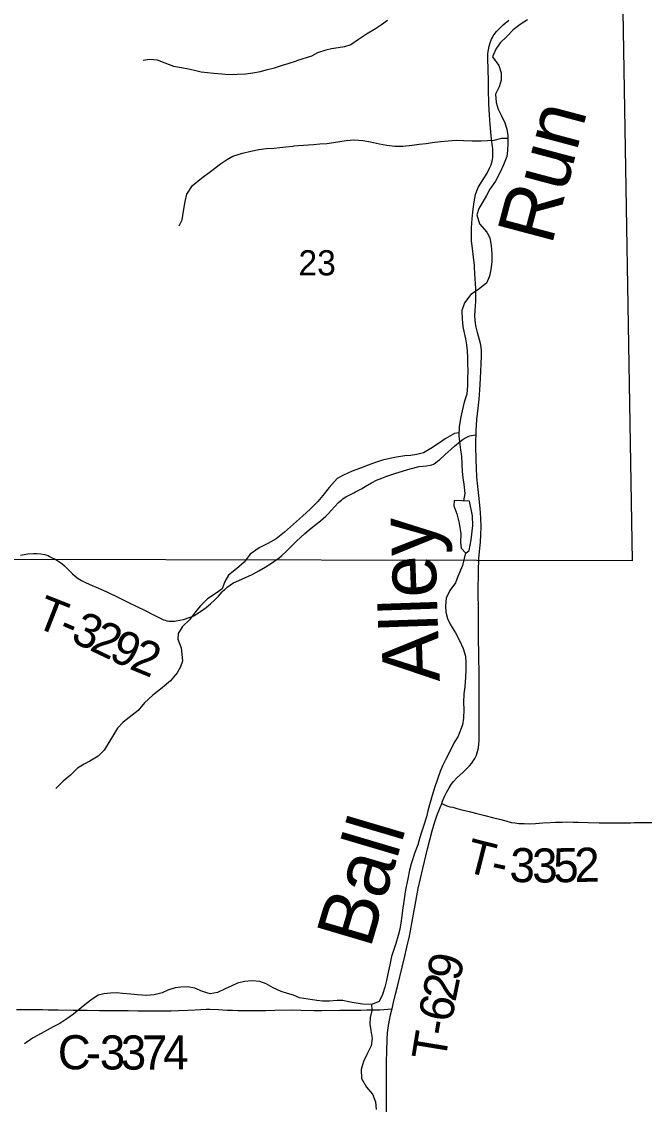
# Model space of a CAD drawing. Extents: x 1874609 to 2204689, y 815661 to 1281160.
# Drawn here: x 2035487 to 2040964, y 935118 to 944638 of the extents above; entities that cross this region are included whole.
import ezdxf

# ---------------------------------------------------------------- set-up
doc = ezdxf.new("R2010")
doc.units = 0
for name, color, linetype in [('GM_X_County_Road', 7, 'Continuous'), ('GM_X_County_Road_Text', 7, 'Continuous'), ('GM_X_Minor_Lake', 7, 'Continuous'), ('GM_X_Minor_River', 7, 'Continuous'), ('GM_X_Minor_River_Text', 7, 'Continuous'), ('GM_X_Section', 7, 'Continuous'), ('GM_X_Section_Text', 7, 'Continuous'), ('GM_X_Township_Road', 7, 'Continuous'), ('GM_X_Township_Road_Text', 7, 'Continuous')]:
    doc.layers.add(name, color=color, linetype=linetype)

msp = doc.modelspace()

# ---------------------------------------------------------------- linework, layer by layer
at = {"layer": 'GM_X_County_Road'}
msp.add_lwpolyline([(2035441, 935952.1), (2035490.1, 935952.7), (2035571.9, 935953), (2035621, 935952.2), (2035670.1, 935950.8), (2035719.3, 935948), (2035807.1, 935948.3), (2035940.9, 935947), (2036011.3, 935946.3), (2036064.3, 935945.8), (2036170.5, 935944.7), (2036315.9, 935943.3), (2036424.4, 935942.3), (2036507.5, 935941.5), (2036588.2, 935940.7), (2036589.7, 935940.7), (2036670.9, 935941.5), (2036736.2, 935941.2), (2036801.6, 935941.1), (2036867, 935942.4), (2036948.6, 935946), (2037013.7, 935949.5), (2037062.3, 935951.9), (2037110.3, 935954.2), (2037141.5, 935954.2), (2037217.8, 935951.4), (2037293.9, 935947.3), (2037340.5, 935945.2), (2037388, 935943.6), (2037420.1, 935942.9), (2037452.6, 935942.7), (2037632.7, 935943.6), (2037714.5, 935944.9), (2037861.8, 935948.2), (2037943.8, 935947.8), (2038058.3, 935944.2), (2038123.4, 935943.5), (2038286.9, 935946.8), (2038385, 935946.9), (2038471.2, 935947.2), (2038523.9, 935947.9), (2038569.5, 935948.1), (2038600, 935948.8), (2038638.7, 935950.3), (2038673.4, 935951.8), (2038707.6, 935954.5), (2038745, 935958)], dxfattribs=at)
at = {"layer": 'GM_X_Minor_Lake'}
for points in [[(2039292.2, 940427), (2039288.6, 940380.9), (2039313.2, 940311), (2039334, 940227), (2039348.8, 940135), (2039345.5, 940060.8), (2039352, 940008.8), (2039392.4, 939965.1), (2039424.2, 939989.4), (2039441.4, 940081.8), (2039454.3, 940208.1), (2039453.5, 940294.2), (2039426.3, 940422.2)], [(2039426.3, 940422.2), (2039292.2, 940427)]]:
    msp.add_lwpolyline(points, dxfattribs=at)
at = {"layer": 'GM_X_Minor_River'}
for points in [[(2038705.7, 944648.6), (2038652, 944610), (2038598.2, 944573.5), (2038520.6, 944526.7), (2038450.9, 944480), (2038383.2, 944435.3), (2038327.3, 944416.7), (2038271.4, 944408.2), (2038213.4, 944397.7), (2038161.4, 944387.2), (2038089.6, 944362.4), (2038037.8, 944333.9), (2037904.7, 944293.3)], [(2039937, 944653.9), (2039871.3, 944613.3), (2039809.6, 944566.6), (2039754.1, 944506), (2039696.6, 944451.4), (2039657, 944394.9), (2039629.6, 944328.6), (2039684.3, 944253), (2039704.9, 944189), (2039705.5, 944122.9), (2039688, 944064.7), (2039654.6, 944000.3), (2039659.2, 943926.2), (2039677.8, 943868.2), (2039704.3, 943814.4), (2039736.9, 943748.6), (2039753.4, 943692.7), (2039761.9, 943636.7), (2039764.5, 943570.5), (2039761.1, 943504.4), (2039753.6, 943452.3), (2039726.2, 943377.9), (2039698.7, 943319.5), (2039653.4, 943235), (2039606, 943164.4), (2039574.4, 943110), (2039542.9, 943053.7), (2039509.4, 942995.2), (2039491.9, 942939), (2039514.6, 942861.1), (2039579.3, 942787.5), (2039603.8, 942735.7), (2039616.4, 942669.7), (2039621.1, 942595.6), (2039621.7, 942525.5), (2039612.3, 942457.3), (2039600.8, 942401.1), (2039575.4, 942338.8), (2039497.8, 942277.9), (2039438.1, 942239.3), (2039382.7, 942164.7), (2039359.3, 942098.4), (2039362, 942022.3), (2039368.5, 941958.2), (2039379, 941902.2), (2039391.5, 941850.3), (2039400, 941796.2), (2039404.5, 941742.2), (2039409.1, 941682.1), (2039409.5, 941632.1), (2039410.1, 941565.9), (2039408.6, 941503.8), (2039409.2, 941439.7), (2039401.9, 941361.5), (2039378.5, 941291.2), (2039361.2, 941214.9), (2039347.8, 941148.7), (2039334.4, 941076.4), (2039333.1, 940996.3), (2039337.6, 940942.2), (2039346.2, 940874.2), (2039354.8, 940814.2), (2039357.3, 940750.1), (2039361.9, 940682), (2039368.4, 940628), (2039377, 940570), (2039385.7, 940489.9), (2039373.7, 940424.1)], [(2036555.6, 944299.3), (2036613.7, 944309.4), (2036677.7, 944301.5), (2036747.8, 944275.6), (2036823.9, 944245.7), (2036894, 944235.8), (2036954, 944223.8), (2037008.1, 944211.9), (2037066.1, 944196), (2037120.2, 944190), (2037178.2, 944184.1), (2037248.3, 944178.2), (2037308.3, 944174.3), (2037382.4, 944176.4), (2037458.4, 944178.5), (2037520.5, 944188.6), (2037586.5, 944198.7), (2037638.5, 944212.8), (2037710.6, 944230.9), (2037780.6, 944255), (2037832.6, 944271.1), (2037904.7, 944293.3)], [(2039762.9, 943611.6), (2039706.1, 943610.1), (2039640.2, 943593.4), (2039584.1, 943590.9), (2039528.1, 943586.4), (2039450, 943587.7), (2039371.9, 943591), (2039307.8, 943592.4), (2039237.8, 943585.7), (2039171.8, 943581.1), (2039097.8, 943572.4), (2039045.8, 943563.9), (2038983.8, 943557.3), (2038921.8, 943548.8), (2038839.8, 943540), (2038769.7, 943541.3), (2038699.5, 943548.7), (2038635.4, 943560.1), (2038555.1, 943577.4), (2038486.9, 943590.8), (2038412.8, 943596.2), (2038340.8, 943589.5), (2038228.8, 943572.4), (2038170.8, 943563.9), (2038110.8, 943559.3), (2038054.8, 943554.8), (2037879.4, 943542.5)], [(2036873.4, 942842.4), (2036897.4, 942896.5), (2036911.3, 942972.6), (2036925.2, 943056.7), (2036941.2, 943120.8), (2036989.1, 943196.9), (2037069.1, 943263.1), (2037147.1, 943319.3), (2037237.1, 943387.5), (2037289.1, 943423.6), (2037345.1, 943453.7), (2037429.1, 943481.8), (2037503.2, 943499.9), (2037573.2, 943514.1), (2037641.3, 943522.2), (2037707.3, 943526.3), (2037759.3, 943530.3), (2037809.4, 943536.4), (2037879.4, 943542.5)], [(2039333.5, 941023.6), (2039292.9, 941018), (2039213.2, 940971.2), (2039143.6, 940922.4), (2039085.8, 940883.8), (2039020.1, 940847.2), (2038962.2, 940832.6), (2038908.2, 940824.1), (2038858.2, 940819.6), (2038784.2, 940808.9), (2038724.2, 940796.3), (2038660.3, 940781.7), (2038598.4, 940761.1), (2038534.5, 940738.5), (2038466.7, 940711.8), (2038394.8, 940685.1), (2038317.1, 940650.3), (2038263.3, 940619.8), (2038191.9, 940541), (2038136.5, 940470.4), (2038092.9, 940419.9), (2038025.4, 940351.2), (2037957.9, 940290.4)], [(2037957.9, 940290.4), (2037850.8, 940195.3), (2037798.9, 940149.2), (2037726.9, 940091.1), (2037650.9, 940048.9), (2037574.8, 940010.8), (2037496.8, 939954.6), (2037442.9, 939886.5), (2037376.9, 939826.3), (2037304.9, 939770.2), (2037272.9, 939716.1), (2037251, 939652), (2037197, 939611.9), (2037121, 939561.7), (2037057, 939497.6), (2037015, 939447.5), (2036963, 939379.3), (2036901, 939319.2), (2036865.1, 939259.1), (2036861.1, 939207), (2036889.2, 939131), (2036895.3, 939076.9), (2036901.3, 939014.9), (2036883.4, 938964.8), (2036853.4, 938912.7), (2036795.4, 938840.6), (2036723.4, 938780.4), (2036639.5, 938716.2), (2036567.5, 938648.1), (2036511.5, 938581.9), (2036459.5, 938539.8), (2036379.5, 938477.6), (2036331.5, 938425.5), (2036295.5, 938367.4), (2036263.6, 938313.3), (2036213.6, 938233.2), (2036159.6, 938181), (2036087.6, 938134.9), (2036035.6, 938108.8), (2035979.6, 938072.7), (2035917.6, 938012.5), (2035853.6, 937960.4), (2035787.6, 937894.2)], [(2039391.4, 939966.2), (2039363.3, 939856.7), (2039322.2, 939758.1), (2039302.6, 939703.8), (2039253.2, 939637.3), (2039221.8, 939568.9), (2039214.4, 939500.7), (2039216.8, 939446.6), (2039231.4, 939390.7), (2039257.9, 939334.8), (2039302.5, 939265.1), (2039339.2, 939195.3), (2039369.9, 939125.5), (2039390.5, 939059.6), (2039393, 939003.5), (2039393.6, 938935.4), (2039390.1, 938873.3), (2039384.9, 938789.1), (2039375.4, 938728.9), (2039374.1, 938650.7), (2039376.6, 938590.7), (2039373.3, 938514.5), (2039365.8, 938456.3), (2039326.7, 938355.8), (2039289.2, 938295.4), (2039259.7, 938233), (2039220.3, 938160.5), (2039188.9, 938096.1), (2039167.3, 938043.8), (2039143.9, 937977.5), (2039122.4, 937909.2), (2039099.1, 937834.8), (2039079.6, 937772.5), (2039058.2, 937698.2), (2039046.7, 937646), (2039023.3, 937573.7), (2039007.8, 937519.4), (2038990.3, 937463.2), (2038972.8, 937400.9), (2038945.4, 937332.6), (2038914.2, 937232.1), (2038898.7, 937177.9), (2038883.4, 937101.6), (2038866.1, 937019.3), (2038858.5, 936967.1), (2038847.1, 936902.9), (2038839.6, 936846.8), (2038824.6, 936730.4), (2038813.2, 936658.2), (2038799.7, 936604), (2038778.3, 936533.7), (2038760.8, 936479.4), (2038741.3, 936417.1), (2038725.9, 936344.9), (2038708.6, 936266.6), (2038695.1, 936206.3), (2038681.6, 936148.1), (2038662.1, 936083.8), (2038632.6, 936023.4), (2038564.8, 935996.8), (2038486.7, 935998.1), (2038430.6, 936007.6), (2038362.4, 936021), (2038312.2, 936030.5), (2038262.2, 936032), (2038196.1, 936025.4), (2038132.1, 936026.8), (2038082, 936030.4), (2037931, 936053.5)], [(2037931, 936053.5), (2037876.9, 936077.4), (2037824.9, 936093.4), (2037770.8, 936111.3), (2037698.7, 936143.3), (2037636.6, 936177.2), (2037582.6, 936199.2), (2037514.5, 936205.1), (2037448.5, 936199), (2037386.5, 936184.9), (2037336.4, 936160.8), (2037276.4, 936132.7), (2037210.4, 936100.5), (2037144.4, 936090.4), (2037076.3, 936110.3), (2037010.2, 936140.3), (2036942.2, 936152.2), (2036888.1, 936148.1), (2036836.1, 936142), (2036774.1, 936121.9), (2036722.1, 936097.8), (2036654, 936081.7), (2036588, 936075.6), (2036505.9, 936081.5), (2036445.9, 936087.4), (2036373.8, 936093.3), (2036323.8, 936097.3), (2036269.7, 936097.2), (2036209.7, 936091.1), (2036159.7, 936077), (2036095.7, 936034.9), (2036027.7, 935980.7), (2035941.7, 935912.5), (2035883.7, 935870.4), (2035823.6, 935830.3), (2035763.6, 935800.2), (2035711.6, 935770.1), (2035657.6, 935740), (2035583.6, 935699.8), (2035511.6, 935651.7)], [(2038564.8, 935996.8), (2038567.3, 935944.7), (2038551.8, 935880.5), (2038550.3, 935822.3), (2038556.8, 935768.3), (2038569.5, 935698.3), (2038560, 935634.1), (2038522.7, 935557.6), (2038493.2, 935495.3), (2038471.8, 935424.9), (2038476.5, 935346.8), (2038519.2, 935269.1), (2038571.8, 935207.5), (2038598.4, 935141.6), (2038605, 935071.6)]]:
    msp.add_lwpolyline(points, dxfattribs=at)
at = {"layer": 'GM_X_Section'}
msp.add_lwpolyline([(2035376.2, 945285.5), (2040767.1, 945252.1), (2040855.8, 939898.2), (2035389.4, 939909.3)], close=True, dxfattribs=at)
at = {"layer": 'GM_X_Township_Road'}
for points in [[(2039617.4, 944476.4), (2039620, 944483), (2039627, 944497.8), (2039635, 944512.1), (2039644, 944525.8), (2039664.3, 944551.5), (2039686.2, 944575.8), (2039721.9, 944609.4), (2039772.5, 944651.2)], [(2039468.8, 942493.9), (2039461.5, 942568), (2039449.8, 942665.6), (2039444.9, 942708.8), (2039443.8, 942749.6), (2039443.2, 942777.3), (2039445, 942826.1), (2039450.4, 942907.5), (2039458.2, 942989.3), (2039466.1, 943054.4), (2039471.8, 943086.8), (2039479.8, 943118.6), (2039490.3, 943149.6), (2039503.6, 943179.6), (2039519.2, 943208.4), (2039580.2, 943305.8), (2039603.4, 943349.2), (2039616.1, 943379.4), (2039625.5, 943410.8), (2039628.9, 943426.9), (2039631.2, 943443.1), (2039632.5, 943459.5), (2039632.7, 943476), (2039630.1, 943523.6), (2039629.1, 943539), (2039620.1, 943603.5), (2039607.8, 943734.2), (2039601.5, 943816), (2039596, 943914.3), (2039593.5, 944045.5), (2039592.2, 944127.5), (2039590.3, 944209.4), (2039587.2, 944323.6), (2039588.2, 944356.4), (2039591.8, 944388.9), (2039598.4, 944421), (2039607.9, 944452.4), (2039617.4, 944476.4)], [(2039484.3, 941006.3), (2039485.2, 941042.2), (2039490.7, 941140.3), (2039500.9, 941238.1), (2039510, 941319.3), (2039516, 941401.1), (2039522.6, 941499.2), (2039529.7, 941630.2), (2039531.6, 941695.6), (2039530.6, 941744.6), (2039527.7, 941777.1), (2039522.7, 941809.4), (2039514.9, 941841.2), (2039496, 941904.1), (2039484, 941951.8), (2039478.4, 941984.1), (2039475.2, 942016.7), (2039474.4, 942049.3), (2039476.3, 942098.4), (2039481.5, 942180.1), (2039482.9, 942228.5), (2039482.7, 942244.3), (2039481.2, 942290.7), (2039474.4, 942420.7), (2039469.5, 942486.2), (2039468.8, 942493.9)], [(2035477.6, 939946.2), (2035492.8, 939950.6), (2035508.8, 939954), (2035541, 939958.8), (2035589.9, 939962.7), (2035622.6, 939962.1), (2035655.1, 939958.3), (2035687.8, 939952.3), (2035719.2, 939943.7), (2035730.5, 939936), (2035743.9, 939929.5), (2035787.4, 939909.5), (2035814.8, 939892.7), (2035840.4, 939873.3), (2035864.4, 939851.8), (2035898.6, 939817.2), (2035921.6, 939794.2), (2035933.7, 939783.2), (2035958.9, 939762.3), (2035985.5, 939742.9), (2036013.1, 939725.3), (2036041.9, 939709.5), (2036086.5, 939688.8), (2036161.8, 939656.5), (2036236.6, 939623.6), (2036340.2, 939575.5), (2036427.5, 939532.1), (2036573.6, 939459.8), (2036646.2, 939422.1), (2036704, 939391.9), (2036734, 939379.3), (2036749.6, 939374.3), (2036765.4, 939370.4), (2036781.6, 939367.6), (2036797.8, 939366), (2036814.2, 939365.6), (2036830.5, 939366.3), (2036846.8, 939368.1), (2036878.9, 939374.3), (2036910.5, 939382.7), (2036970.6, 939401.2), (2037000.7, 939413.8), (2037029, 939430), (2037069.5, 939457.9), (2037109, 939487.4), (2037147.5, 939518.2), (2037183.9, 939551.3), (2037218.1, 939586.7), (2037250.1, 939624.1), (2037261.1, 939635.9), (2037273.4, 939646.4), (2037297.6, 939667.4), (2037310.8, 939676.9), (2037335.2, 939696.3), (2037349.6, 939703.7), (2037424.9, 939736.4), (2037514.3, 939777.8), (2037572.4, 939808.1), (2037629, 939841.3), (2037684.2, 939876.8), (2037751.1, 939924), (2037776.2, 939945.1), (2037812.4, 939978.3), (2037905.6, 940070.9), (2037941.2, 940104.9), (2037977.8, 940137.7), (2038015.1, 940169), (2038078, 940218.3), (2038114.8, 940247.8), (2038139.6, 940268.3), (2038163.7, 940290.3), (2038186.7, 940313.7), (2038208.3, 940338.3), (2038240.4, 940375.4), (2038274.4, 940410.3), (2038298.9, 940431.5), (2038311.6, 940441.2), (2038324.8, 940450.1), (2038338.4, 940458.6), (2038366.6, 940474.4), (2038409.6, 940496.1), (2038423.7, 940503.7), (2038480.7, 940534.2), (2038494.7, 940542.2), (2038509, 940549.8), (2038565, 940582.8), (2038608.6, 940605.3), (2038653.6, 940625.2), (2038699.6, 940642.6), (2038777.4, 940668.1), (2038903.1, 940704.9), (2038982.4, 940725.2), (2039014.7, 940730.1), (2039046.9, 940733.5), (2039078.9, 940737.6), (2039094.4, 940741.8), (2039109.1, 940748.4), (2039122.9, 940757), (2039148.8, 940776.1), (2039160.9, 940786.4), (2039208.2, 940828.6), (2039294.1, 940904.8), (2039343.6, 940946.5), (2039370, 940965.6), (2039398.2, 940982.2), (2039414, 940989.9), (2039429, 940995.6), (2039444.4, 941000.3), (2039461, 941003.4), (2039479.4, 941005.7), (2039484.3, 941006.3)], [(2039181.5, 937763.5), (2039190, 937785.2), (2039208.5, 937830.3), (2039222.6, 937859.7), (2039247.3, 937902.4), (2039265.7, 937929.6), (2039285.8, 937955.5), (2039318.9, 937991.8), (2039366.8, 938036.7), (2039403.2, 938069.8), (2039425.9, 938093.5), (2039446.9, 938118.7), (2039456.5, 938132), (2039472.5, 938160.5), (2039486.3, 938189.5), (2039496.7, 938220.3), (2039503.9, 938252.4), (2039508.4, 938284.8), (2039510.7, 938317.4), (2039512.4, 938399.3), (2039512.5, 938628.7), (2039511.4, 938792.4), (2039510.6, 938939.9), (2039509.6, 939021.8), (2039507.5, 939120.1), (2039506.4, 939169), (2039506, 939201.1), (2039505.9, 939281.5), (2039505.7, 939330.4), (2039505.3, 939395.8), (2039504.5, 939461.5), (2039502.4, 939625.5), (2039503.8, 939806.1), (2039508, 939916.7), (2039514.7, 939980.3), (2039522.9, 940061.5), (2039526.7, 940127.2), (2039527.3, 940192.8), (2039524.7, 940274.7), (2039519.7, 940356.6), (2039509.1, 940470.9), (2039499.7, 940552.1), (2039491.7, 940633.6), (2039486.4, 940715.4), (2039484.1, 940780.8), (2039482.6, 940911.6), (2039483.1, 940960.6), (2039484.3, 941006.3)], [(2038745, 935958), (2038756.1, 936001.2), (2038776.4, 936086.8), (2038795.3, 936166.6), (2038834.1, 936325.8), (2038856.9, 936421.5), (2038876.3, 936501.2), (2038898.3, 936597.1), (2038907.9, 936645.1), (2038922.9, 936725.6), (2038934.7, 936790.1), (2038948.9, 936870.8), (2038969.2, 936983.6), (2038975.6, 937015.5), (2039016, 937191), (2039056.8, 937363.9), (2039097.9, 937522.7), (2039121, 937601.3), (2039142.5, 937663.3), (2039181.5, 937763.5)], [(2039181.5, 937763.5), (2039195.9, 937756.4), (2039206.8, 937752), (2039215.4, 937748.4), (2039227.6, 937744.3), (2039254.2, 937735.6), (2039278.7, 937729.8), (2039313.4, 937720.3), (2039359.3, 937709.1), (2039424.1, 937692.6), (2039490.4, 937675.7), (2039559.8, 937658.1), (2039628.4, 937640.7), (2039690.1, 937625), (2039746.9, 937610.6), (2039794, 937597.8), (2039826.1, 937592.3), (2039858.6, 937589), (2039907.6, 937586.2), (2039956.6, 937586), (2040005.6, 937588), (2040070.8, 937594.1), (2040135, 937597.1), (2040181.1, 937599.3), (2040240.8, 937600.5), (2040283.5, 937601.3), (2040337.9, 937600.2), (2040382.3, 937598.1), (2040469.8, 937596.3), (2040565.6, 937594.2), (2040659.6, 937594.2), (2040745.4, 937594.2), (2040809.7, 937594.2), (2040842.6, 937594.2), (2040874.9, 937595.1), (2040939.9, 937596.9), (2041037.9, 937597.8)], [(2038385, 934328.5), (2038451.4, 934441.8), (2038523.8, 934570.4), (2038630.4, 934755.3), (2038654, 934798.5), (2038667.7, 934828.3), (2038678.7, 934859.3), (2038686.8, 934891.1), (2038692, 934923.5), (2038695.7, 934972.6), (2038696.7, 935087.7), (2038696.3, 935186.3), (2038695.3, 935268.5), (2038694.6, 935416.2), (2038695.5, 935498.3), (2038698, 935580.1), (2038702.5, 935694.7), (2038705.8, 935743.8), (2038711, 935792.7), (2038721.1, 935857.4), (2038731.4, 935905.4), (2038742.5, 935948.4), (2038745, 935958)]]:
    msp.add_lwpolyline(points, dxfattribs=at)

# ---------------------------------------------------------------- texts
at = {"layer": 'GM_X_County_Road_Text'}
for s, rotation, p in [('C', 359.76777, (2035804.4, 935426.7)), ('3', 359.77576, (2036174.1, 935425.2)), ('3', 359.82144, (2036359.1, 935424.5)), ('7', 359.98113, (2036544.8, 935423.9)), ('4', 0.56025, (2036733, 935423.8)), ('-', 359.76192, (2036050.8, 935425.7))]:
    msp.add_text(s, height=300, rotation=rotation, dxfattribs=at).set_placement(p)
at = {"layer": 'GM_X_Minor_River_Text'}
for s, height, rotation, p in [('Run', 500.1, 75.09685, (2040147.6, 942663.1)), ('Alley', 500.11, 91.9823, (2039165.5, 938837.9)), ('Ball', 500.13, 73.48962, (2038552.1, 936479.1))]:
    msp.add_text(s, height=height, rotation=rotation, dxfattribs=at).set_placement(p)
at = {"layer": 'GM_X_Section_Text'}
msp.add_text('23', height=221, rotation=0.00001, dxfattribs=at).set_placement((2037921.7, 942407.4))
at = {"layer": 'GM_X_Township_Road_Text'}
for s, rotation, p in [('T', 338.60925, (2035588.9, 939321.1)), ('3', 335.45785, (2035907.2, 939192.7)), ('-', 336.94901, (2035795.8, 939240.1)), ('2', 334.54516, (2036074.2, 939116.5)), ('9', 334.70608, (2036241.9, 939036.6)), ('2', 337.65886, (2036424.4, 938950.9)), ('T', 345.7382, (2039372.2, 937168.9)), ('3', 357.04328, (2039773.7, 937077.5)), ('3', 0.62761, (2039978.7, 937067.5)), ('5', 0.9683, (2040165.4, 937069.6)), ('2', 1.07035, (2040350.8, 937072.7)), ('-', 347.60454, (2039600, 937111.1)), ('9', 77.0202, (2039337.7, 936191)), ('2', 78.58545, (2039301.6, 936012)), ('6', 79.65558, (2039268.7, 935831.6)), ('T', 80.71522, (2039212.2, 935490.1)), ('-', 80.42409, (2039248.4, 935711.2))]:
    msp.add_text(s, height=300, rotation=rotation, dxfattribs=at).set_placement(p)

doc.saveas('drawing.dxf')
